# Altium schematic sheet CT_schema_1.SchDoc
size 465 x 455 mm
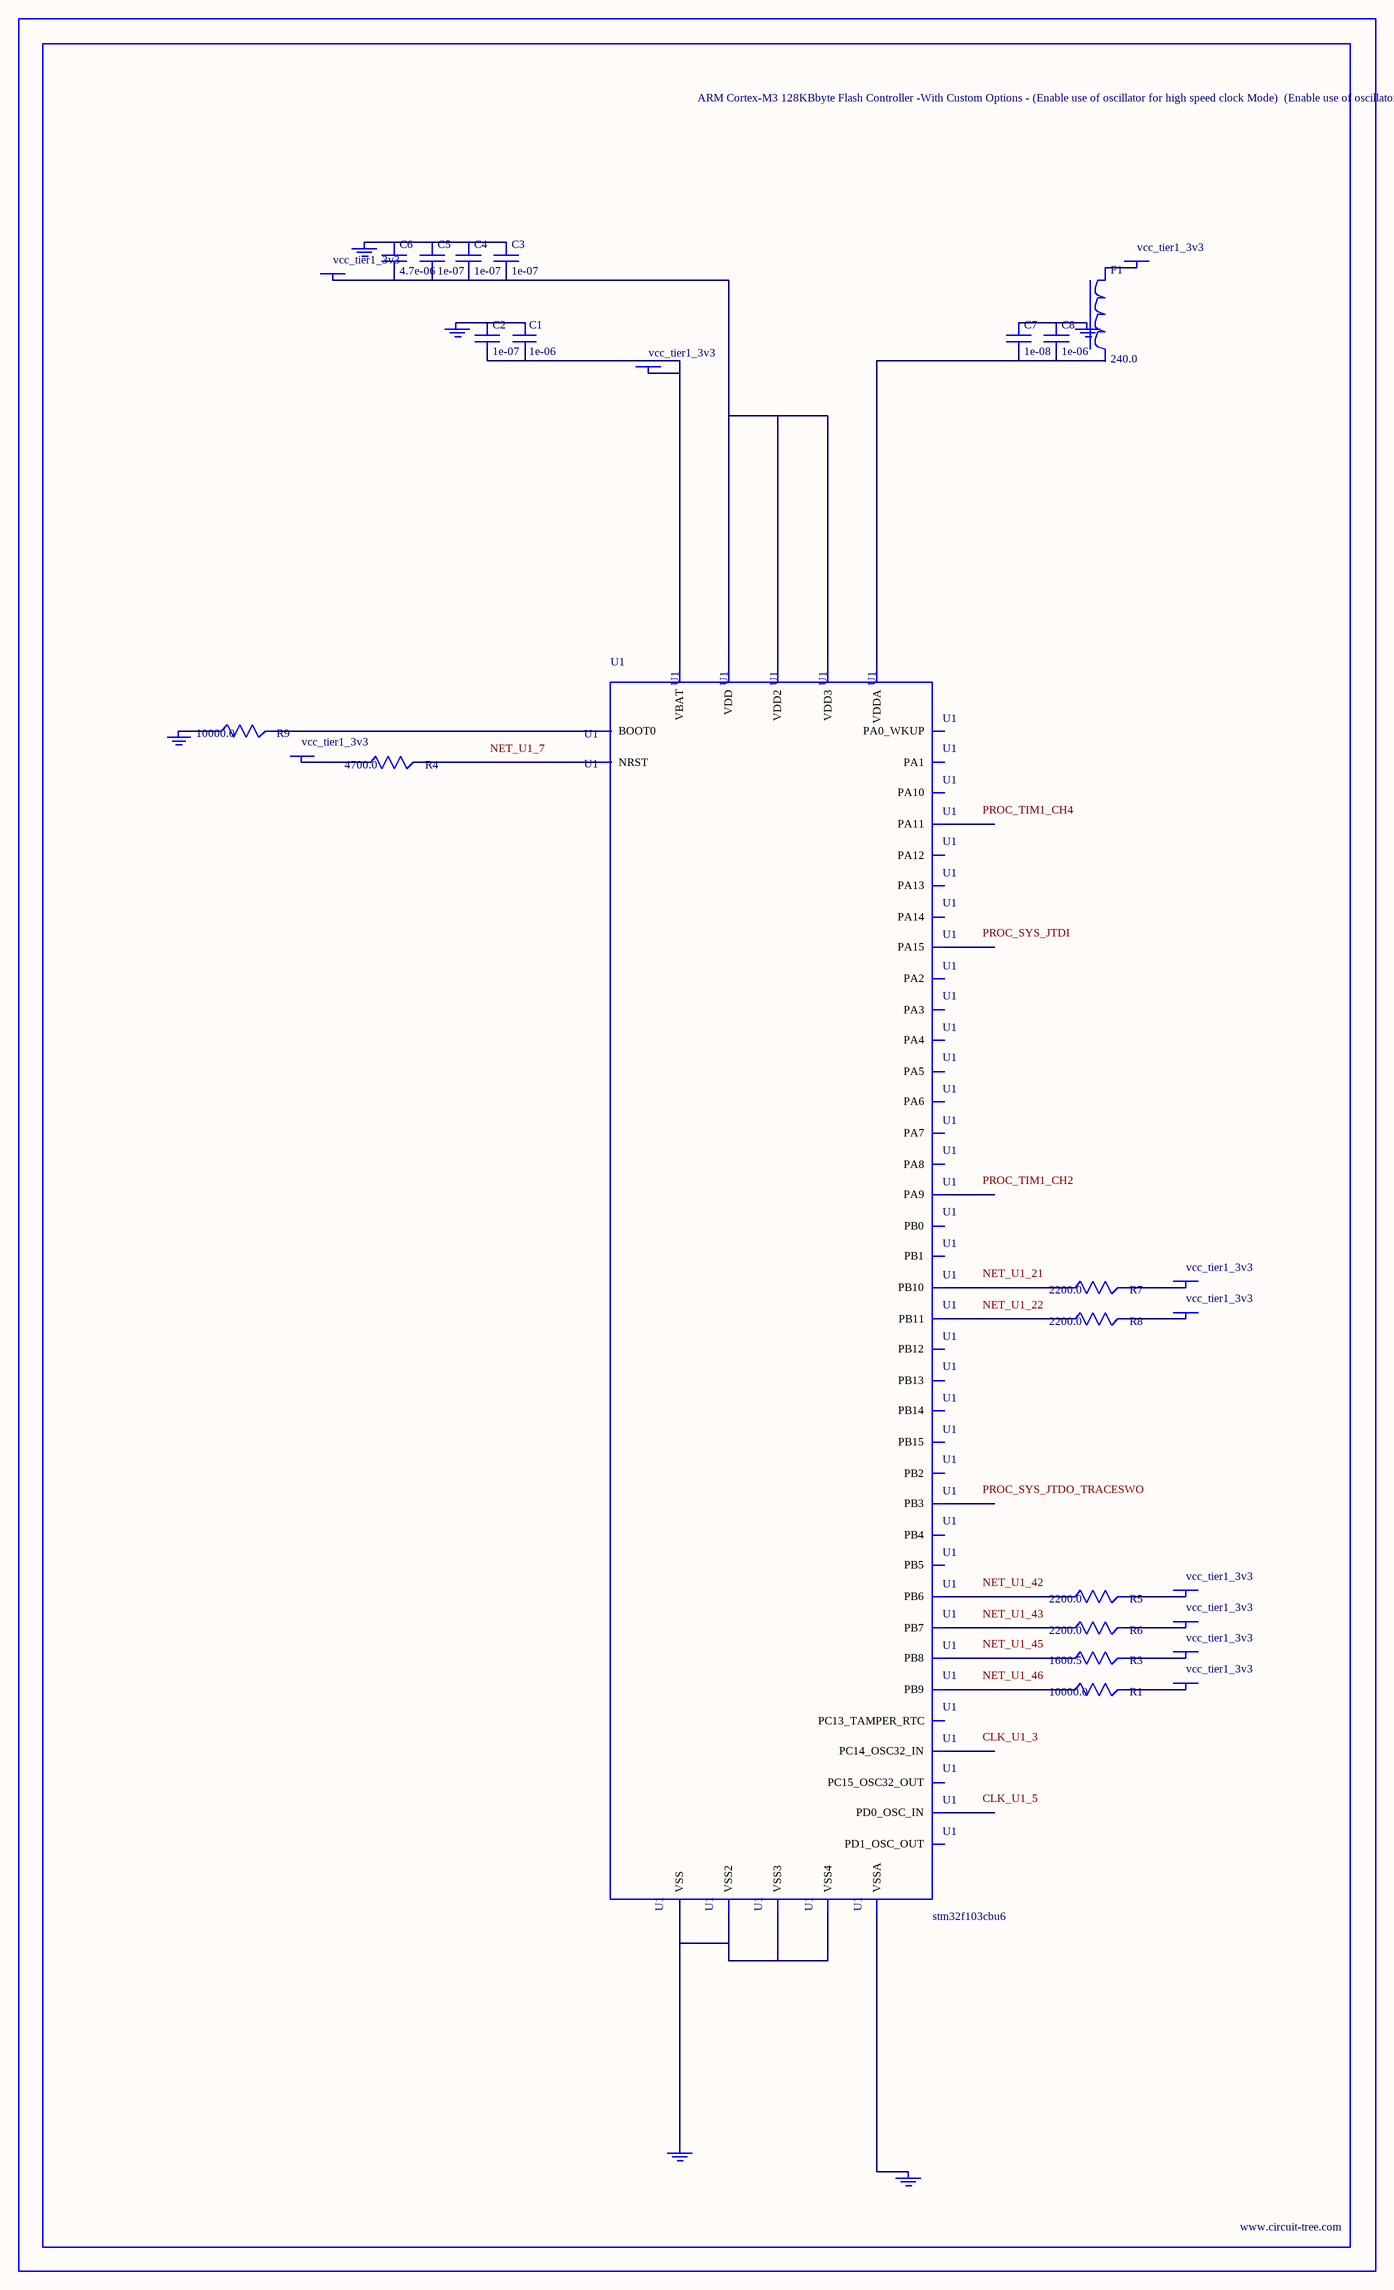
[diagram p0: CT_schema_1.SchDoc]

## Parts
BORDER0  (no value)
C1  1e-06  [C0603]
C2  1e-07  [C0603]
C3  1e-07  [C0603]
C4  1e-07  [C0603]
C5  1e-07  [C0603]
C6  4.7e-06  [C0603]
C7  1e-08  [C0603]
C8  1e-06  [C0603]
F1  240.0  [L0603]
GND_INSTANCE_0_0  (no value)
GND_INSTANCE_0_1  (no value)
GND_INSTANCE_0_2  (no value)
GND_INSTANCE_0_3  (no value)
GND_INSTANCE_0_4  (no value)
GND_INSTANCE_0_5  (no value)
POWER_INSTANCE_0_0  vcc_tier1_3v3
POWER_INSTANCE_0_1  vcc_tier1_3v3
POWER_INSTANCE_0_2  vcc_tier1_3v3
POWER_INSTANCE_0_3  vcc_tier1_3v3
POWER_INSTANCE_0_4  vcc_tier1_3v3
POWER_INSTANCE_0_5  vcc_tier1_3v3
POWER_INSTANCE_0_6  vcc_tier1_3v3
POWER_INSTANCE_0_7  vcc_tier1_3v3
POWER_INSTANCE_0_8  vcc_tier1_3v3
POWER_INSTANCE_0_9  vcc_tier1_3v3
R1  10000.0  [R0603]
R3  1600.5  [R0603]
R4  4700.0  [R0603]
R5  2200.0  [R0603]
R6  2200.0  [R0603]
R7  2200.0  [R0603]
R8  2200.0  [R0603]
R9  10000.0  [R0603]
U1  stm32f103cbu6  [UFQFPN48]

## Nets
NetC1_1: C1.1 C2.1 GND_INSTANCE_0_0.0(GND)
NetC1_2: C1.2 C2.2 POWER_INSTANCE_0_0.0(PWR) U1.1(VBAT)
NetC3_1: C3.1 C4.1 C5.1 C6.1 GND_INSTANCE_0_3.0(GND)
NetC3_2: C3.2 C4.2 C5.2 C6.2 POWER_INSTANCE_0_2.0(PWR) U1.24(VDD) U1.36(VDD2) U1.48(VDD3)
NetC7_1: C7.1 C8.1 GND_INSTANCE_0_2.0(GND)
NetC7_2: C7.2 C8.2 U1.9(VDDA)
NetF1_1: F1.1 POWER_INSTANCE_0_1.0(PWR)
NetGND_INSTANCE_0_1_0: GND_INSTANCE_0_1.0(GND) U1.8(VSSA)
NetGND_INSTANCE_0_4_0: GND_INSTANCE_0_4.0(GND) R9.1
NetGND_INSTANCE_0_5_0: GND_INSTANCE_0_5.0(GND) U1.23(VSS) U1.35(VSS2) U1.47(VSS3) U1.49(VSS4)
NetPOWER_INSTANCE_0_3_0: POWER_INSTANCE_0_3.0(PWR) R4.1
NetPOWER_INSTANCE_0_4_0: POWER_INSTANCE_0_4.0(PWR) R7.2
NetPOWER_INSTANCE_0_5_0: POWER_INSTANCE_0_5.0(PWR) R8.2
NetPOWER_INSTANCE_0_6_0: POWER_INSTANCE_0_6.0(PWR) R5.2
NetPOWER_INSTANCE_0_7_0: POWER_INSTANCE_0_7.0(PWR) R6.2
NetPOWER_INSTANCE_0_8_0: POWER_INSTANCE_0_8.0(PWR) R3.2
NetPOWER_INSTANCE_0_9_0: POWER_INSTANCE_0_9.0(PWR) R1.2
NetR1_1: R1.1 U1.46(PB9)
NetR3_1: R3.1 U1.45(PB8)
NetR4_2: R4.2 U1.7(NRST)
NetR5_1: R5.1 U1.42(PB6)
NetR6_1: R6.1 U1.43(PB7)
NetR7_1: R7.1 U1.21(PB10)
NetR8_1: R8.1 U1.22(PB11)
NetR9_2: R9.2 U1.44(BOOT0)

Not connected (* = marked no-connect by the designer): F1 2; U1 2(PC13_TAMPER_RTC) 3(PC14_OSC32_IN) 4(PC15_OSC32_OUT) 5(PD0_OSC_IN) 6(PD1_OSC_OUT) 10(PA0_WKUP) 11(PA1) 12(PA2) 13(PA3) 14(PA4) 15(PA5) 16(PA6) 17(PA7) 18(PB0) 19(PB1) 20(PB2) 25(PB12) 26(PB13) 27(PB14) 28(PB15) 29(PA8) 30(PA9) 31(PA10) 32(PA11) 33(PA12) 34(PA13) 37(PA14) 38(PA15) 39(PB3) 40(PB4) 41(PB5)

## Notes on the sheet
- Labels drawn without touching a wire or pin: CLK_U1_3, CLK_U1_5, NET_U1_7, NET_U1_21, NET_U1_22, NET_U1_42, NET_U1_43, NET_U1_45, NET_U1_46, PROC_SYS_JTDI, PROC_SYS_JTDO_TRACESWO, PROC_TIM1_CH2, PROC_TIM1_CH4

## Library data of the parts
BORDER0 = BORDER_PAGE0
C1 C8 = C0603C105K3RACTU
C2-C5 = 06035C104K4Z2A
C6 = GRM188R6YA475KE15D
C7 = 06035C103K4Z2A
F1 = Z0603C241ASMST
GND_INSTANCE_0_0-GND_INSTANCE_0_5 = GND
POWER_INSTANCE_0_0-POWER_INSTANCE_0_9 = PWR
R1 R9 = RC0603JR-0710KL
R3 = R3
R4 = RC0603JR-074K7L
R5-R8 = RC0603JR-072K2L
